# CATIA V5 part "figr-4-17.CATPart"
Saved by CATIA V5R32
Part number: Part1
Bounding box of the stored display mesh (mm): x 0 to 40, y -49.816 to 150, z -49.907 to 49.907
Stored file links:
  D:\PROJECTS\Project 2022\CATIA V5 6R 2022\Resources\Part Files\c04_catia_v5_6r2022_prt\figr-4-17.CATPart
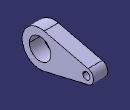
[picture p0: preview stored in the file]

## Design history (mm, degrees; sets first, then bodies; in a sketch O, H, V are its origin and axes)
Body1 (main body)
  Sketch1 on yz-plane, origin (0, 0, 0), H (0, 1, 0), V (0, 0, 1)
    arc A1 centre (0, 0) radius 50 from (11.5385, 48.6504) to (11.5385, -48.6504) ccw
    arc A2 centre (130, 0) radius 20 from (134.6154, -19.4602) to (134.6154, 19.4602) ccw
    point P1 (130, 0)
    line L1 (134.6154, 19.4602) -> (11.5385, 48.6504)
    line L2 (134.6154, -19.4602) -> (11.5385, -48.6504)
    circle A3 centre (0, 0) radius 30
    circle A4 centre (130, 0) radius 10
    point P6 (120, 0)
    coincidence: P1 H, A4 P6, P6 H
    tangency: L1 A2, L1 A1, L2 A2, L2 A1
  Pad1: profile Sketch1, direction (1, 0, 0), length 40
